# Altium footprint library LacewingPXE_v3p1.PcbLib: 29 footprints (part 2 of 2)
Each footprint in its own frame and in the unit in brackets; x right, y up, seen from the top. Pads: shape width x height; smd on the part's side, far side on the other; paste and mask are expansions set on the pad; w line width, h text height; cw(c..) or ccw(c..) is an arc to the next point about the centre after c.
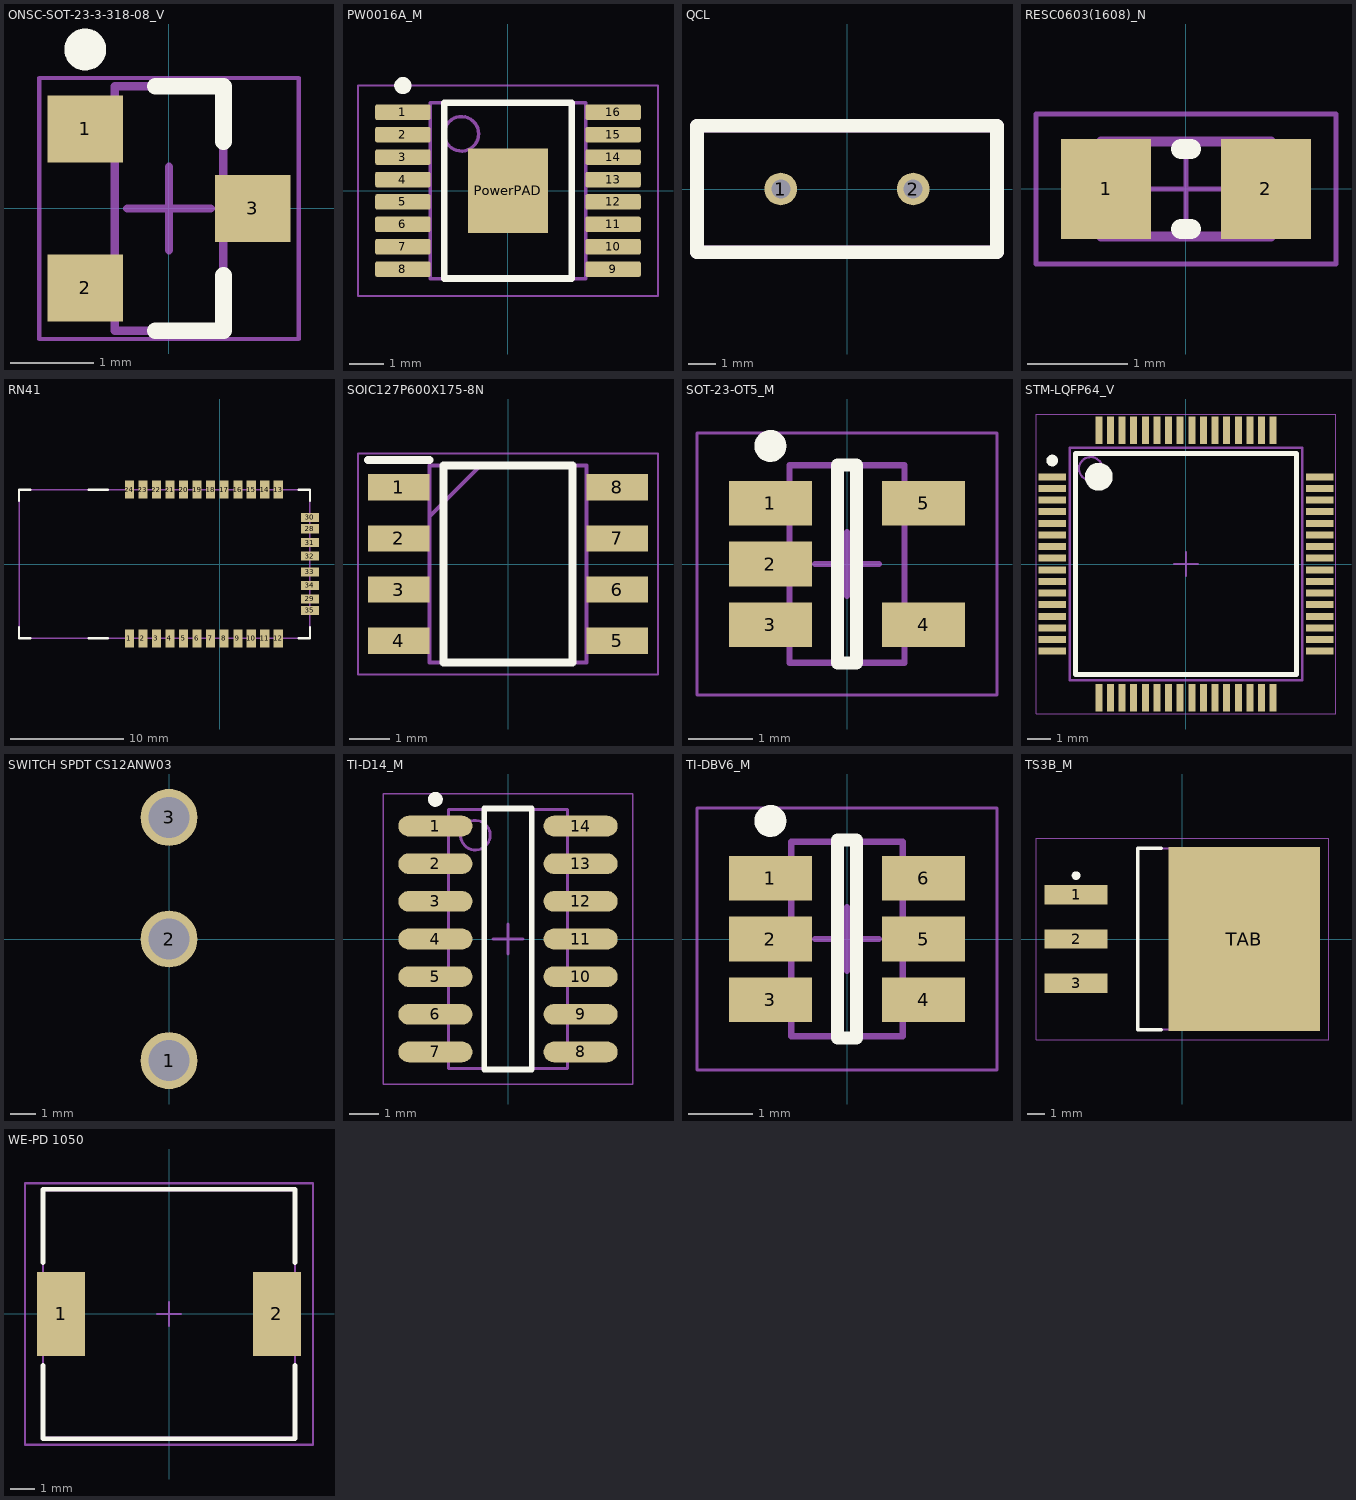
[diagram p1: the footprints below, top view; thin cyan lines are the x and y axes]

## ONSC-SOT-23-3-318-08_V [mm] "SOT23, 3-Leads, Body 2.92x1.3mm, Pitch 0.95mm"
height 1.11
pads (3):
  rect 0.9x0.8 smd: 1(-1,0.95) 2(-1,-0.95) 3(1,0)
Top Overlay:
  circle w0.25: c-1,1.9 r0.125
  lines w0.2: -0.165,-1.46 0.65,-1.46 0.65,-0.8 ; -0.165,1.46 0.65,1.46 0.65,0.8
Mechanical 13:
  lines w0.1: -0.65,-1.46 0.65,-1.46 0.65,1.46 -0.65,1.46 -0.65,-1.46
Mechanical 15:
  lines w0.05: -1.55,-1.56 1.55,-1.56 1.55,1.56 -1.55,1.56 -1.55,-1.56
  lines w0.1: -0.5,0 0.5,0 ; 0,-0.5 0,0.5
3D body: height 1.11, standoff 0.01, extent -0.65,-1.46 0.65,1.46

## PW0016A_M [mm] "SOP, 16-Leads, Body 5.1x4.5mm, Pitch 0.65mm, IPC Low Density"
height 1.2
pads (17):
  rrect22% 1.6x0.45 smd: 1(-3.05,2.275) 2(-3.05,1.625) 3(-3.05,0.975) 4(-3.05,0.325) 5(-3.05,-0.325) 6(-3.05,-0.975) 7(-3.05,-1.625) 8(-3.05,-2.275) 9(3.05,-2.275) 10(3.05,-1.625) 11(3.05,-0.975) 12(3.05,-0.325) 13(3.05,0.325) 14(3.05,0.975) 15(3.05,1.625) 16(3.05,2.275)
  rect 2.31x2.46 smd: PowerPAD(0,0)
Top Overlay:
  circle w0.25: c-3.05,3.05 r0.125
  lines w0.2: -1.85,-2.55 1.85,-2.55 1.85,2.55 -1.85,2.55 -1.85,-2.55
Mechanical 13:
  circle w0.1: c-1.35,1.65 r0.5
  lines w0.1: -2.25,-2.55 2.25,-2.55 2.25,2.55 -2.25,2.55 -2.25,-2.55
Mechanical 15:
  lines w0.05: -4.35,-3.05 4.35,-3.05 4.35,3.05 -4.35,3.05 -4.35,-3.05
  lines w0.1: -0.5,0 0.5,0 ; 0,-0.5 0,0.5
3D body "PW0016AakaMTC16.stp": height 1, standoff 0, extent -3.21,-2.5 3.21,2.5

## QCL [mm]
pads (2):
  round 1.2 hole 0.7: 1(-2.44,0) 2(2.44,0)
Top Overlay:
  lines w0.5: -5.525,-2.325 -5.525,2.325 5.525,2.325 5.525,-2.325 -5.525,-2.325
Mechanical 15:
  lines w0.5: -5.525,-2.325 5.525,-2.325 5.525,2.325 -5.525,2.325 -5.525,-2.325

## RESC0603(1608)_N [mm] "Chip Resistor, Body 1.6x0.8mm, IPC Medium Density"
height 0.6
pads (2):
  rect 0.9x1 smd: 1(-0.8,0) 2(0.8,0)
Top Overlay:
  lines w0.2: -0.05,-0.4 0.05,-0.4 ; -0.05,0.4 0.05,0.4
Mechanical 13:
  lines w0.1: -0.85,-0.475 -0.85,0.475 0.85,0.475 0.85,-0.475 -0.85,-0.475
Mechanical 15:
  lines w0.05: -0.475,0 0.475,0 ; 0,-0.475 0,0.475 ; -1.5,-0.75 -1.5,0.75 1.5,0.75 1.5,-0.75 -1.5,-0.75
3D body: height 0.6, standoff 0, extent 0.581,-0.474 0.85,0.475
3D body: height 0.6, standoff 0, extent -0.58,-0.474 0.581,0.475
3D body: height 0.6, standoff 0, extent -0.849,-0.474 -0.58,0.475

## RN41 [mil]
pads (32):
  rect 32x63 smd: 1(-315.42,-259.92) 2(-268.18,-259.92) 3(-220.93,-259.92) 4(-173.69,-259.92) 5(-126.44,-259.92) 6(-79.2,-259.92) 7(-31.58,-259.92) 8(15.42,-259.92) 9(63.42,-259.92) 10(110.42,-259.92) 11(157.42,-259.92) 12(204.42,-259.92) 13(204.42,259.92) 14(157.42,259.92) 15(110.42,259.92) 16(63.42,259.92) 17(15.42,259.92) 18(-31.58,259.92) 19(-79.2,259.92) 20(-126.44,259.92) 21(-173.69,259.92) 22(-220.93,259.92) 23(-268.18,259.92) 24(-315.42,259.92)
  rect 63x32 smd: 28(315.42,122.92) 29(315.42,-122.13) 30(315.42,162.92) 31(315.42,74.92) 32(315.42,27.92) 33(315.42,-27.64) 34(315.42,-74.88) 35(315.42,-162.37)
Top Overlay:
  lines w8: -701.25,-220.55 -701.25,-259.92 -661.88,-259.92 ; -701.25,220.92 -701.25,259.92 -661.88,259.92 ; -457.15,-259.92 -390.22,-259.92 ; -457.15,259.92 -390.22,259.92 ; 275.42,-259.92 315.42,-259.92 315.42,-220.55 ; 275.42,259.92 315.42,259.92 315.42,220.92
Mechanical 16:
  lines w5: -701.25,-259.92 315.42,-259.92 315.42,259.92 -701.25,259.92 -701.25,-259.92

## SOIC127P600X175-8N [mm]
pads (8):
  rect 1.525x0.65 smd: 1(-2.712,1.905) 2(-2.712,0.635) 3(-2.712,-0.635) 4(-2.712,-1.905) 5(2.712,-1.905) 6(2.712,-0.635) 7(2.712,0.635) 8(2.712,1.905)
Top Overlay:
  lines w0.2: -3.475,2.58 -1.95,2.58 ; -1.6,-2.45 -1.6,2.45 1.6,2.45 1.6,-2.45 -1.6,-2.45
Mechanical 13:
  lines w0.1: -1.95,1.18 -0.68,2.45 ; -1.95,-2.45 -1.95,2.45 1.95,2.45 1.95,-2.45 -1.95,-2.45
Mechanical 15:
  lines w0.05: -3.725,-2.75 -3.725,2.75 3.725,2.75 3.725,-2.75 -3.725,-2.75
3D body "NE555DR.stp": height 1.75, standoff 0, extent -3,-2.45 3,2.45

## SOT-23-OT5_M [mm] "SOT23, 5-Leads, Body 2.9x1.7mm, Pitch 0.95mm, Lead Span 2.8mm, IPC Low Density"
height 1.45
pads (5):
  rect 1.3x0.7 smd: 1(-1.2,0.95) 2(-1.2,0) 3(-1.2,-0.95) 4(1.2,-0.95) 5(1.2,0.95)
Top Overlay:
  circle w0.25: c-1.2,1.85 r0.125
  lines w0.2: -0.15,-1.55 -0.15,1.55 0.15,1.55 0.15,-1.55 -0.15,-1.55
Mechanical 13:
  lines w0.1: -0.9,-1.55 0.9,-1.55 0.9,1.55 -0.9,1.55 -0.9,-1.55
Mechanical 15:
  lines w0.05: -2.35,-2.05 2.35,-2.05 2.35,2.05 -2.35,2.05 -2.35,-2.05
  lines w0.1: -0.5,0 0.5,0 ; 0,-0.5 0,0.5
3D body: height 1.45, standoff 0, extent -0.9,-1.55 0.9,1.55

## STM-LQFP64_V [mm] "Thin QFP, 64-Leads, Body 10x10mm, Pitch 0.5mm, ST Recommended"
height 1.6
pads (64):
  rect 1.2x0.3 smd: 1(-5.75,3.75) 2(-5.75,3.25) 3(-5.75,2.75) 4(-5.75,2.25) 5(-5.75,1.75) 6(-5.75,1.25) 7(-5.75,0.75) 8(-5.75,0.25) 9(-5.75,-0.25) 10(-5.75,-0.75) 11(-5.75,-1.25) 12(-5.75,-1.75) 13(-5.75,-2.25) 14(-5.75,-2.75) 15(-5.75,-3.25) 16(-5.75,-3.75) 33(5.75,-3.75) 34(5.75,-3.25) 35(5.75,-2.75) 36(5.75,-2.25) 37(5.75,-1.75) 38(5.75,-1.25) 39(5.75,-0.75) 40(5.75,-0.25) 41(5.75,0.25) 42(5.75,0.75) 43(5.75,1.25) 44(5.75,1.75) 45(5.75,2.25) 46(5.75,2.75) 47(5.75,3.25) 48(5.75,3.75)
  rect 0.3x1.2 smd: 17(-3.75,-5.75) 18(-3.25,-5.75) 19(-2.75,-5.75) 20(-2.25,-5.75) 21(-1.75,-5.75) 22(-1.25,-5.75) 23(-0.75,-5.75) 24(-0.25,-5.75) 25(0.25,-5.75) 26(0.75,-5.75) 27(1.25,-5.75) 28(1.75,-5.75) 29(2.25,-5.75) 30(2.75,-5.75) 31(3.25,-5.75) 32(3.75,-5.75) 49(3.75,5.75) 50(3.25,5.75) 51(2.75,5.75) 52(2.25,5.75) 53(1.75,5.75) 54(1.25,5.75) 55(0.75,5.75) 56(0.25,5.75) 57(-0.25,5.75) 58(-0.75,5.75) 59(-1.25,5.75) 60(-1.75,5.75) 61(-2.25,5.75) 62(-2.75,5.75) 63(-3.25,5.75) 64(-3.75,5.75)
Top Overlay:
  circle w0.25: c-5.75,4.45 r0.125
  circle w0.6: c-3.75,3.75 r0.3
  lines w0.2: -4.75,-4.75 -4.75,4.75 4.75,4.75 4.75,-4.75 -4.75,-4.75
Mechanical 13:
  circle w0.1: c-4.1,4.1 r0.5
  lines w0.1: -5,-5 -5,5 5,5 5,-5 -5,-5
Mechanical 15:
  lines w0.05: -6.45,-6.45 -6.45,6.45 6.45,6.45 6.45,-6.45 -6.45,-6.45
  lines w0.1: -0.5,0 0.5,0 ; 0,-0.5 0,0.5
3D body: height 1.6, standoff 0.05, extent -5,-5 5,5

## SWITCH SPDT CS12ANW03 [mm]
pads (3):
  round 2.2 hole 1.6: 1(0,-4.7) 2(0,0) 3(0,4.7)

## TI-D14_M [mm] "SOIC, 14-Leads, Body 8.65x3.9mm, Pitch 1.27mm, IPC Low Density"
height 1.75
pads (14):
  oval 2.5x0.7 smd: 1(-2.45,3.81) 2(-2.45,2.54) 3(-2.45,1.27) 4(-2.45,0) 5(-2.45,-1.27) 6(-2.45,-2.54) 7(-2.45,-3.81) 8(2.45,-3.81) 9(2.45,-2.54) 10(2.45,-1.27) 11(2.45,0) 12(2.45,1.27) 13(2.45,2.54) 14(2.45,3.81)
Top Overlay:
  circle w0.25: c-2.45,4.71 r0.125
  lines w0.2: -0.8,-4.4 -0.8,4.4 0.8,4.4 0.8,-4.4 -0.8,-4.4
Mechanical 13:
  circle w0.1: c-1.1,3.5 r0.5
  lines w0.1: -2,-4.375 -2,4.375 2,4.375 2,-4.375 -2,-4.375
Mechanical 15:
  lines w0.05: -4.2,-4.9 -4.2,4.9 4.2,4.9 4.2,-4.9 -4.2,-4.9
  lines w0.1: -0.5,0 0.5,0 ; 0,-0.5 0,0.5
3D body: height 1.75, standoff 0.1, extent -2,-4.375 2,4.375

## TI-DBV6_M [mm] "SOT-23, 6-Leads, Body 2.90x1.60mm, Pitch 0.95mm, IPC Low Density"
height 1.45
pads (6):
  rect 1.3x0.7 smd: 1(-1.2,0.95) 2(-1.2,0) 3(-1.2,-0.95) 4(1.2,-0.95) 5(1.2,0) 6(1.2,0.95)
Top Overlay:
  circle w0.25: c-1.2,1.85 r0.125
  lines w0.2: -0.15,-1.55 0.15,-1.55 0.15,1.55 -0.15,1.55 -0.15,-1.55
Mechanical 13:
  lines w0.1: -0.875,-1.525 -0.875,1.525 0.875,1.525 0.875,-1.525 -0.875,-1.525
Mechanical 15:
  lines w0.05: -2.35,-2.05 -2.35,2.05 2.35,2.05 2.35,-2.05 -2.35,-2.05
  lines w0.1: -0.5,0 0.5,0 ; 0,-0.5 0,0.5
3D body: height 1.45, standoff 0, extent -0.875,-1.525 0.875,1.525

## TS3B_M [mm] "D2-PAK, 4-Leads, Body 8.6x10.2mm, Pitch 2.54mm, Lead Span 14.2mm, IPC Low Density"
height 4.64
pads (4):
  rect 3.6x1.1 smd: 1(-6.1,2.54) 2(-6.1,0) 3(-6.1,-2.54)
  rect 8.7x10.55 smd: TAB(3.55,0)
Top Overlay:
  circle w0.25: c-6.1,3.64 r0.125
  lines w0.2: -1.2,-5.2 -2.55,-5.2 -2.55,5.2 -1.2,5.2
Mechanical 13:
  lines w0.1: -2.55,-5.2 6.34,-5.2 6.34,5.2 -2.55,5.2 -2.55,-5.2
Mechanical 15:
  lines w0.05: -8.4,-5.775 8.4,-5.775 8.4,5.775 -8.4,5.775 -8.4,-5.775
  lines w0.1: -0.5,0 0.5,0 ; 0,-0.5 0,0.5
3D body: height 4.64, standoff 0, extent -2.55,-5.2 6.34,5.2

## WE-PD 1050 [mm] "SMD Inductor, 2-Leads, Body 10,0x10,0mm"
height 5
pads (2):
  rect 2x3.5 smd: 1(-4.5,0) 2(4.5,0)
Top Overlay:
  lines w0.2: -5.25,-2.15 -5.25,-5.2 5.25,-5.2 5.25,-2.15 ; -5.25,2.15 -5.25,5.2 5.25,5.2 5.25,2.15
Mechanical 13:
  lines w0.1: -5.25,-5.15 -5.25,5.15 5.25,5.15 5.25,-5.15 -5.25,-5.15
Mechanical 15:
  lines w0.1: -0.5,0 0.5,0 ; 0,-0.5 0,0.5 ; -6,-5.45 -6,5.45 6,5.45 6,-5.45 -6,-5.45
3D body "7447714xx.stp": height 4.75, standoff -0.05, extent -5,-5 5,5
